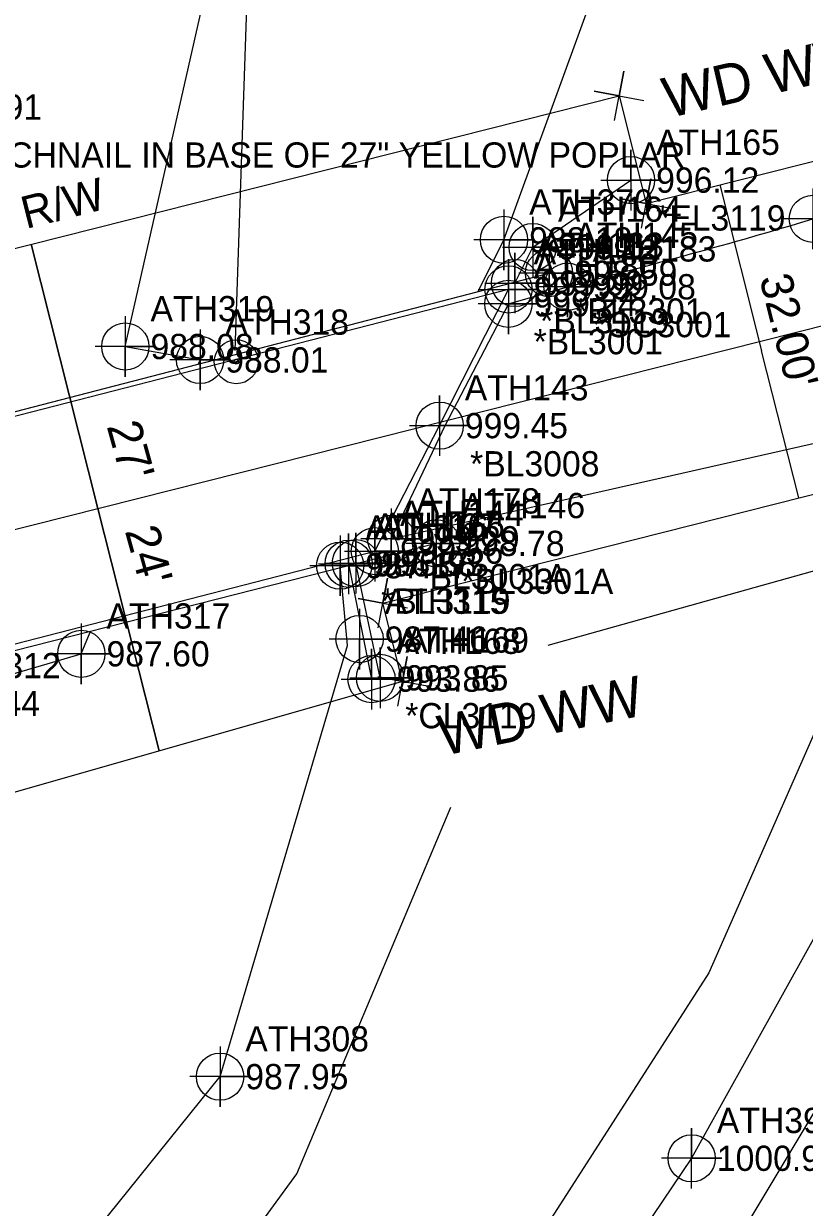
# Model space of a CAD drawing. Extents: x 1116345 to 1117546, y 660629 to 661859.
# Drawn here: x 1117048.4 to 1117125.8, y 661296.1 to 661413.4 of the extents above; entities that cross this region are included whole.
import ezdxf

# ---------------------------------------------------------------- set-up
doc = ezdxf.new("R2010")
doc.units = 0
for name, color, linetype in [('CTL Vertical Benchmark Cogo Comment', 7, 'Continuous'), ('CTL Vertical Benchmark Cogo Elevation', 7, 'Continuous'), ('Exist DTM Crownline Cogo Comment', 7, 'Continuous'), ('Exist DTM Drainline Cogo Elevation', 7, 'Continuous'), ('Exist DTM Drainline Cogo Number', 7, 'Continuous'), ('Exist DTM Drainline Cogo Point CELL', 7, 'Continuous'), ('Exist Guardrail', 7, 'Continuous'), ('Exist Guardrail Cogo Comment', 7, 'Continuous'), ('Exist Guardrail Cogo Elevation', 7, 'Continuous'), ('Exist Guardrail Cogo Number', 7, 'Continuous'), ('Exist Guardrail Cogo Point CELL', 7, 'Continuous'), ('Exist Horizontal Alignment', 7, 'Continuous'), ('Exist Hydro Jurisdictional Stream or Body of Water', 7, 'Continuous'), ('Exist Property Corner CELL', 7, 'Continuous'), ('Exist Right of Way Line', 7, 'Continuous'), ('Exist Right of Way Line Text', 7, 'Continuous'), ('Exist Right of Way Width CELL', 7, 'Continuous'), ('Exist Roads EOP', 7, 'Continuous'), ('Exist Roads EOP Cogo Comment', 7, 'Continuous'), ('Exist Roads EOP Cogo Elevation', 7, 'Continuous'), ('Exist Roads EOP Cogo Number', 7, 'Continuous'), ('Exist Roads EOP Cogo Point CELL', 7, 'Continuous'), ('Exist Roads Soil', 7, 'Continuous'), ('Exist Roads Soil Cogo Elevation', 7, 'Continuous'), ('Exist Roads Soil Cogo Number', 7, 'Continuous'), ('Exist Roads Soil Cogo Point CELL', 7, 'Continuous'), ('Exist Structure Major Bridge Seam Cogo Elevation', 7, 'Continuous'), ('Exist Structure Major Bridge Seam Cogo Number', 7, 'Continuous'), ('Exist Structure Major Bridge Seam Cogo Point CELL', 7, 'Continuous'), ('Exist Structure Major Bridge WW', 7, 'Continuous'), ('Exist Structure Major Bridge WW Cogo Comment', 7, 'Continuous'), ('Exist Structure Major Bridge WW Cogo Elevation', 7, 'Continuous'), ('Exist Structure Major Bridge WW Cogo Number', 7, 'Continuous'), ('Exist Structure Major Bridge WW Cogo Point CELL', 7, 'Continuous'), ('Exist Structure Major Bridge WW Text', 7, 'Continuous'), ('Exist Structure Major Deck Tunnel Box Culvert', 7, 'Continuous'), ('Exist Utilities Other Located Object CELL', 7, 'Continuous'), ('Exist Utilities Power Pole Leader', 7, 'Continuous'), ('Exist Vegetation Woods Line', 7, 'Continuous')]:
    doc.layers.add(name, color=color, linetype=linetype)

msp = doc.modelspace()

# ---------------------------------------------------------------- linework, layer by layer
at = {"layer": 'Exist DTM Drainline Cogo Point CELL'}
for points in [[(1117095.99, 661394.98), (1117095.99, 661388.98), (1117095.99, 661391.98), (1117098.99, 661391.98), (1117092.99, 661391.98)], [(1117058.44, 661384.41), (1117058.44, 661378.41), (1117058.44, 661381.41), (1117061.44, 661381.41), (1117055.44, 661381.41)], [(1117065.86, 661383.08), (1117065.86, 661377.08), (1117065.86, 661380.08), (1117068.86, 661380.08), (1117062.86, 661380.08)], [(1117079.75, 661362.69), (1117079.75, 661356.69), (1117079.75, 661359.69), (1117082.75, 661359.69), (1117076.75, 661359.69)], [(1117081.67, 661355.42), (1117081.67, 661349.42), (1117081.67, 661352.42), (1117084.67, 661352.42), (1117078.67, 661352.42)], [(1117054.08, 661353.96), (1117054.08, 661347.96), (1117054.08, 661350.96), (1117057.08, 661350.96), (1117051.08, 661350.96)], [(1117067.84, 661312.06), (1117067.84, 661306.06), (1117067.84, 661309.06), (1117070.84, 661309.06), (1117064.84, 661309.06)]]:
    msp.add_lwpolyline(points, dxfattribs=at)
for centre in [(1117095.99, 661391.98), (1117058.44, 661381.41), (1117065.86, 661380.08), (1117079.75, 661359.69), (1117081.67, 661352.42), (1117054.08, 661350.96), (1117067.84, 661309.06)]:
    msp.add_circle(centre, 2.34, dxfattribs=at)
at = {"layer": 'Exist Guardrail'}
for p, q in [((1117026, 661369.4), (1117100.46, 661388.68)), ((1117089.27, 661361.9), (1117017.81, 661343.69))]:
    msp.add_line(p, q, dxfattribs=at)
at = {"layer": 'Exist Guardrail Cogo Point CELL'}
for points in [[(1117100.46, 661391.68), (1117100.46, 661385.68), (1117100.46, 661388.68), (1117103.46, 661388.68), (1117097.46, 661388.68)], [(1117089.27, 661364.9), (1117089.27, 661358.9), (1117089.27, 661361.9), (1117092.27, 661361.9), (1117086.27, 661361.9)]]:
    msp.add_lwpolyline(points, dxfattribs=at)
for centre in [(1117100.46, 661388.68), (1117089.27, 661361.9)]:
    msp.add_circle(centre, 2.34, dxfattribs=at)
at = {"layer": 'Exist Horizontal Alignment'}
msp.add_line((1117026.39, 661357.95), (1117138.69, 661386.3), dxfattribs=at)
at = {"layer": 'Exist Hydro Jurisdictional Stream or Body of Water'}
msp.add_line((1117095.99, 661391.98), (1117093.41, 661386.86), dxfattribs=at)
for points in [[(1117058.44, 661381.41), (1117066.56, 661417.27), (1117077.35, 661449.25), (1117098.92, 661488.98)], [(1117095.99, 661391.98), (1117110.73, 661432.45), (1117125.36, 661468.03)], [(1117058.44, 661381.41), (1117065.86, 661380.08), (1117065.68, 661379.69)], [(1116999.25, 661212.66), (1117035.55, 661269.03), (1117067.84, 661309.06), (1117080.47, 661351.77), (1117079.75, 661359.69)], [(1117037.26, 661346.04), (1117054.08, 661350.96), (1117054.96, 661353.12)]]:
    msp.add_lwpolyline(points, dxfattribs=at)
at = {"layer": 'Exist Property Corner CELL'}
for p, q in [((1117107.4, 661406.25), (1117107.4, 661406.25)), ((1117110.1, 661395.59), (1117110.1, 661395.59)), ((1117083.98, 661355.99), (1117083.98, 661355.99)), ((1117085.94, 661348.23), (1117085.94, 661348.23))]:
    msp.add_line(p, q, dxfattribs=at)
for points in [[(1117106.94, 661403.79), (1117107.86, 661408.71), (1117107.4, 661406.25), (1117104.95, 661406.71), (1117109.86, 661405.79)], [(1117109.64, 661393.13), (1117110.55, 661398.04), (1117110.1, 661395.59), (1117107.64, 661396.04), (1117112.55, 661395.13)], [(1117083.52, 661353.53), (1117084.44, 661358.45), (1117083.98, 661355.99), (1117081.52, 661356.45), (1117086.43, 661355.53)], [(1117085.48, 661345.77), (1117086.39, 661350.69), (1117085.94, 661348.23), (1117083.48, 661348.69), (1117088.39, 661347.77)]]:
    msp.add_lwpolyline(points, dxfattribs=at)
at = {"layer": 'Exist Right of Way Line'}
for p, q in [((1117025.97, 661385.69), (1117107.4, 661406.25)), ((1117107.4, 661406.25), (1117110.1, 661395.59)), ((1117110.1, 661395.59), (1117134.78, 661401.82)), ((1117083.98, 661355.99), (1117142.61, 661370.79)), ((1117085.94, 661348.23), (1117083.98, 661355.99)), ((1117085.94, 661348.23), (1117008.99, 661326.26))]:
    msp.add_line(p, q, dxfattribs=at)
at = {"layer": 'Exist Right of Way Width CELL'}
for p, q in [((1117117.4, 661397.43), (1117121.54, 661380.99)), ((1117049.12, 661391.54), (1117055.73, 661365.36)), ((1117055.73, 661365.36), (1117049.12, 661391.54)), ((1117125.23, 661366.4), (1117121.54, 661380.99)), ((1117061.79, 661341.34), (1117055.73, 661365.36)), ((1117055.73, 661365.36), (1117061.79, 661341.34))]:
    msp.add_line(p, q, dxfattribs=at)
at = {"layer": 'Exist Roads EOP'}
for p, q in [((1117096.43, 661385.64), (1117102.29, 661387.33)), ((1117084.81, 661362.36), (1117131.33, 661372.86))]:
    msp.add_line(p, q, dxfattribs=at)
msp.add_lwpolyline([(1117096.43, 661385.64), (1117090.13, 661373.54), (1117084.81, 661362.36)], dxfattribs=at)
msp.add_spline([(1117102.29, 661387.33), (1117126.62, 661394.06), (1117156.42, 661404.98), (1117187.2, 661421.69), (1117219.89, 661448.41), (1117247.01, 661480.82), (1117275.55, 661531.18), (1117296.66, 661577.27), (1117320.8, 661635.68)], degree=3, dxfattribs=at)
at = {"layer": 'Exist Roads EOP Cogo Point CELL'}
for points in [[(1117126.62, 661397.06), (1117126.62, 661391.06), (1117126.62, 661394.06), (1117129.62, 661394.06), (1117123.62, 661394.06)], [(1117102.29, 661390.33), (1117102.29, 661384.33), (1117102.29, 661387.33), (1117105.29, 661387.33), (1117099.29, 661387.33)], [(1117096.43, 661388.64), (1117096.43, 661382.64), (1117096.43, 661385.64), (1117099.43, 661385.64), (1117093.43, 661385.64)], [(1117084.81, 661365.36), (1117084.81, 661359.36), (1117084.81, 661362.36), (1117087.81, 661362.36), (1117081.81, 661362.36)]]:
    msp.add_lwpolyline(points, dxfattribs=at)
for centre in [(1117126.62, 661394.06), (1117102.29, 661387.33), (1117096.43, 661385.64), (1117084.81, 661362.36)]:
    msp.add_circle(centre, 2.34, dxfattribs=at)
at = {"layer": 'Exist Roads Soil'}
for points in [[(1117086.62, 661238.67), (1117107.74, 661273.83), (1117132.45, 661314.97), (1117148.91, 661339.08), (1117168.41, 661383.47)], [(1117136.15, 661374.23), (1117145.4, 661365.55), (1117144.42, 661353.97), (1117129.29, 661327.4), (1117114.6, 661300.97), (1117095.55, 661272.76), (1117079.49, 661243.19)]]:
    msp.add_lwpolyline(points, dxfattribs=at)
at = {"layer": 'Exist Roads Soil Cogo Point CELL'}
msp.add_lwpolyline([(1117114.6, 661297.97), (1117114.6, 661303.97), (1117114.6, 661300.97), (1117117.6, 661300.97), (1117111.6, 661300.97)], dxfattribs=at)
msp.add_circle((1117114.6, 661300.97), 2.34, dxfattribs=at)
at = {"layer": 'Exist Structure Major Bridge Seam Cogo Point CELL'}
for points in [[(1117093.44, 661387.07), (1117099.44, 661387.07), (1117096.44, 661387.07), (1117096.44, 661390.07), (1117096.44, 661384.07)], [(1117086.61, 661373.57), (1117092.61, 661373.57), (1117089.61, 661373.57), (1117089.61, 661376.57), (1117089.61, 661370.57)], [(1117080.19, 661361.13), (1117086.19, 661361.13), (1117083.19, 661361.13), (1117083.19, 661364.13), (1117083.19, 661358.13)]]:
    msp.add_lwpolyline(points, dxfattribs=at)
for centre in [(1117096.44, 661387.07), (1117089.61, 661373.57), (1117083.19, 661361.13)]:
    msp.add_circle(centre, 2.34, dxfattribs=at)
at = {"layer": 'Exist Structure Major Bridge WW'}
for points in [[(1117097.08, 661387.7), (1117098.84, 661391.27), (1117108.58, 661397.9)], [(1117081.31, 661359.94), (1117080.59, 661359.88), (1117082.86, 661348.45), (1117083.7, 661348.58), (1117081.31, 661359.94)]]:
    msp.add_lwpolyline(points, dxfattribs=at)
at = {"layer": 'Exist Structure Major Bridge WW Cogo Point CELL'}
for points in [[(1117105.58, 661397.9), (1117111.58, 661397.9), (1117108.58, 661397.9), (1117108.58, 661400.9), (1117108.58, 661394.9)], [(1117095.84, 661391.27), (1117101.84, 661391.27), (1117098.84, 661391.27), (1117098.84, 661394.27), (1117098.84, 661388.27)], [(1117094.08, 661387.7), (1117100.08, 661387.7), (1117097.08, 661387.7), (1117097.08, 661390.7), (1117097.08, 661384.7)], [(1117077.59, 661359.88), (1117083.59, 661359.88), (1117080.59, 661359.88), (1117080.59, 661362.88), (1117080.59, 661356.88)], [(1117078.31, 661359.94), (1117084.31, 661359.94), (1117081.31, 661359.94), (1117081.31, 661362.94), (1117081.31, 661356.94)], [(1117079.86, 661348.45), (1117085.86, 661348.45), (1117082.86, 661348.45), (1117082.86, 661351.45), (1117082.86, 661345.45)], [(1117080.7, 661348.58), (1117086.7, 661348.58), (1117083.7, 661348.58), (1117083.7, 661351.58), (1117083.7, 661345.58)]]:
    msp.add_lwpolyline(points, dxfattribs=at)
for centre in [(1117108.58, 661397.9), (1117098.84, 661391.27), (1117097.08, 661387.7), (1117080.59, 661359.88), (1117081.31, 661359.94), (1117082.86, 661348.45), (1117083.7, 661348.58)]:
    msp.add_circle(centre, 2.34, dxfattribs=at)
at = {"layer": 'Exist Structure Major Deck Tunnel Box Culvert'}
msp.add_lwpolyline([(1117020.55, 661345.01), (1117083.19, 661361.13), (1117089.61, 661373.57), (1117096.44, 661387.07), (1117031.74, 661370.43), (1117020.55, 661345.01)], dxfattribs=at)
at = {"layer": 'Exist Utilities Other Located Object CELL'}
for radius in [2.18, 0.24]:
    msp.add_circle((1117069.45, 661379.9), radius, dxfattribs=at)
at = {"layer": 'Exist Utilities Power Pole Leader'}
msp.add_line((1117069.35, 661381.02), (1117073.4, 661500.16), dxfattribs=at)
at = {"layer": 'Exist Vegetation Woods Line'}
for points in [[(1117100.38, 661351.82), (1117134.85, 661361.45), (1117116.32, 661319.34), (1117068.02, 661244.2)], [(1116995.5, 661178.21), (1117040.75, 661251.89), (1117075.44, 661299.42), (1117090.71, 661335.76)]]:
    msp.add_lwpolyline(points, dxfattribs=at)

# ---------------------------------------------------------------- texts
at = {"layer": 'CTL Vertical Benchmark Cogo Comment'}
msp.add_text('BENCHNAIL IN BASE OF 27" YELLOW POPLAR', height=2.5, dxfattribs=at).set_placement((1117039.96, 661399.14))
at = {"layer": 'CTL Vertical Benchmark Cogo Elevation'}
msp.add_text('995.91', height=2.5, dxfattribs=at).set_placement((1117039.96, 661403.89))
at = {"layer": 'Exist DTM Crownline Cogo Comment'}
msp.add_text('*BL3008', height=2.5, dxfattribs=at).set_placement((1117092.63, 661368.54))
at = {"layer": 'Exist DTM Drainline Cogo Elevation'}
for s, p in [('988.18', (1117098.49, 661390.73)), ('988.08', (1117060.94, 661380.16)), ('988.01', (1117068.36, 661378.83)), ('987.17', (1117082.25, 661358.44)), ('987.46', (1117084.17, 661351.17)), ('987.60', (1117056.58, 661349.71)), ('987.44', (1117039.76, 661344.79)), ('987.95', (1117070.34, 661307.81))]:
    msp.add_text(s, height=2.5, dxfattribs=at).set_placement(p)
at = {"layer": 'Exist DTM Drainline Cogo Number'}
for s, p in [('ATH370', (1117098.49, 661394.48)), ('ATH319', (1117060.94, 661383.91)), ('ATH318', (1117068.36, 661382.58)), ('ATH316', (1117082.25, 661362.19)), ('ATH315', (1117084.17, 661354.92)), ('ATH317', (1117056.58, 661353.46)), ('ATH312', (1117039.76, 661348.54)), ('ATH308', (1117070.34, 661311.56))]:
    msp.add_text(s, height=2.5, dxfattribs=at).set_placement(p)
at = {"layer": 'Exist Guardrail Cogo Comment'}
for s, p in [('*BL3301', (1117102.96, 661383.68)), ('*BL3301A', (1117091.77, 661356.9))]:
    msp.add_text(s, height=2.5, dxfattribs=at).set_placement(p)
at = {"layer": 'Exist Guardrail Cogo Elevation'}
for s, p in [('998.59', (1117102.96, 661387.43)), ('998.78', (1117091.77, 661360.65))]:
    msp.add_text(s, height=2.5, dxfattribs=at).set_placement(p)
at = {"layer": 'Exist Guardrail Cogo Number'}
for s, p in [('ATH145', (1117102.96, 661391.18)), ('ATH146', (1117091.77, 661364.4))]:
    msp.add_text(s, height=2.5, dxfattribs=at).set_placement(p)
at = {"layer": 'Exist Right of Way Line Text'}
msp.add_text('EXISTING R/W', height=3.2, rotation=14.1667, dxfattribs=at).set_placement((1117028.07, 661387.87))
at = {"layer": 'Exist Right of Way Width CELL'}
for s, height, rotation, p in [("32.00'", 3.2, 284.1667, (1117121.3, 661388.18)), ("27'", 3.375, 285.5182, (1117056.58, 661373.53)), ("24'", 3.375, 285.5182, (1117058.38, 661363.15))]:
    msp.add_text(s, height=height, rotation=rotation, dxfattribs=at).set_placement(p)
at = {"layer": 'Exist Roads EOP Cogo Comment'}
for s, p in [('*OC3001', (1117104.79, 661382.33)), ('*BL3001', (1117098.93, 661380.64)), ('*BL3001A', (1117087.31, 661357.36))]:
    msp.add_text(s, height=2.5, dxfattribs=at).set_placement(p)
at = {"layer": 'Exist Roads EOP Cogo Elevation'}
for s, p in [('999.08', (1117104.79, 661386.08)), ('999.24', (1117098.93, 661384.39)), ('999.29', (1117087.31, 661361.11))]:
    msp.add_text(s, height=2.5, dxfattribs=at).set_placement(p)
at = {"layer": 'Exist Roads EOP Cogo Number'}
for s, p in [('ATH183', (1117104.79, 661389.83)), ('ATH180', (1117098.93, 661388.14)), ('ATH178', (1117087.31, 661364.86))]:
    msp.add_text(s, height=2.5, dxfattribs=at).set_placement(p)
at = {"layer": 'Exist Roads Soil Cogo Elevation'}
msp.add_text('1000.93', height=2.5, dxfattribs=at).set_placement((1117117.1, 661299.72))
at = {"layer": 'Exist Roads Soil Cogo Number'}
msp.add_text('ATH394', height=2.5, dxfattribs=at).set_placement((1117117.1, 661303.47))
at = {"layer": 'Exist Structure Major Bridge Seam Cogo Elevation'}
for s, p in [('999.22', (1117098.94, 661385.82)), ('999.45', (1117092.11, 661372.32)), ('999.56', (1117085.69, 661359.88))]:
    msp.add_text(s, height=2.5, dxfattribs=at).set_placement(p)
at = {"layer": 'Exist Structure Major Bridge Seam Cogo Number'}
for s, p in [('ATH142', (1117098.94, 661389.57)), ('ATH143', (1117092.11, 661376.07)), ('ATH144', (1117085.69, 661363.63))]:
    msp.add_text(s, height=2.5, dxfattribs=at).set_placement(p)
at = {"layer": 'Exist Structure Major Bridge WW Cogo Comment'}
for s, p in [('*EL3119', (1117111.08, 661392.9)), ('*BL3119', (1117099.58, 661382.7)), ('*BL3119', (1117083.81, 661354.94)), ('*CL3119', (1117086.2, 661343.58))]:
    msp.add_text(s, height=2.5, dxfattribs=at).set_placement(p)
at = {"layer": 'Exist Structure Major Bridge WW Cogo Elevation'}
for s, p in [('996.12', (1117111.08, 661396.65)), ('999.12', (1117101.34, 661390.02)), ('999.09', (1117099.58, 661386.45)), ('996.58', (1117083.09, 661358.63)), ('996.93', (1117083.81, 661358.69)), ('993.86', (1117085.36, 661347.2)), ('993.85', (1117086.2, 661347.33))]:
    msp.add_text(s, height=2.5, dxfattribs=at).set_placement(p)
at = {"layer": 'Exist Structure Major Bridge WW Cogo Number'}
for s, p in [('ATH165', (1117111.08, 661400.4)), ('ATH164', (1117101.34, 661393.77)), ('ATH163', (1117099.58, 661390.2)), ('ATH167', (1117083.09, 661362.38)), ('ATH166', (1117083.81, 661362.44)), ('ATH168', (1117085.36, 661350.95)), ('ATH169', (1117086.2, 661351.08))]:
    msp.add_text(s, height=2.5, dxfattribs=at).set_placement(p)
at = {"layer": 'Exist Structure Major Bridge WW Text'}
for rotation, p in [(12.9999, (1117112.29, 661404.03)), (11.4318, (1117089.94, 661340.84))]:
    msp.add_text('WD WW', height=4, rotation=rotation, dxfattribs=at).set_placement(p)

doc.saveas('drawing.dxf')
